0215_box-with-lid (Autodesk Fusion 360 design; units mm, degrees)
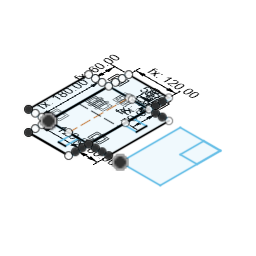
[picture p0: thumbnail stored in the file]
parameter "length" = 180
parameter "width" = 120
parameter "height" = 60
parameter "thickness" = 4.4
sketch "Sketch1" plane through (0, 0, 0) normal (0, 0, 1) x axis (1, 0, 0)
  line L1 (120, 0) -> (0, 0)
  line L2 (120, 180) -> (120, 0)
  line L3 (0, 180) -> (120, 180)
  line L4 (0, 0) -> (0, 180)
  line L5 (180, 0) -> (120, 0)
  line L6 (180, 180) -> (180, 0)
  line L7 (120, 180) -> (180, 180)
  line L8 (120, 0) -> (120, 180)
  line L9 (120, 240) -> (120, 180)
  line L10 (0, 240) -> (120, 240)
  line L11 (0, 180) -> (0, 240)
  line L12 (120, 184.4) -> (120, 180)
  line L13 (130, 184.4) -> (120, 184.4)
  line L14 (130, 180) -> (130, 184.4)
  line L15 (140, 180) -> (130, 180)
  line L16 (150, 184.4) -> (140, 184.4)
  line L17 (150, 180) -> (150, 184.4)
  line L18 (160, 180) -> (150, 180)
  line L19 (140, 184.4) -> (140, 180)
  line L20 (170, 184.4) -> (160, 184.4)
  line L21 (170, 180) -> (170, 184.4)
  line L22 (180, 180) -> (170, 180)
  line L23 (160, 184.4) -> (160, 180)
  line L24 (120, 190) -> (120, 180)
  line L25 (124.4, 190) -> (120, 190)
  line L26 (124.4, 200) -> (124.4, 190)
  line L27 (120, 200) -> (124.4, 200)
  line L28 (120, 210) -> (120, 200)
  line L29 (124.4, 210) -> (120, 210)
  line L30 (124.4, 220) -> (124.4, 210)
  line L31 (120, 220) -> (124.4, 220)
  line L32 (120, 230) -> (120, 220)
  line L33 (124.4, 230) -> (120, 230)
  line L34 (124.4, 240) -> (124.4, 230)
  line L35 (120, 240) -> (124.4, 240)
  line L36 (120, 90) -> (0, 90)
  line L37 (60, 0) -> (60, 180)
  line L38 (-60, 0) -> (0, 0)
  line L39 (-60, 180) -> (-60, 0)
  line L40 (0, 180) -> (-60, 180)
  line L41 (0, 0) -> (0, 180)
  line L42 (120, -60) -> (120, 0)
  line L43 (0, -60) -> (120, -60)
  line L44 (0, 0) -> (0, -60)
  line L45 (0, 210) -> (0, 200)
  line L46 (0, 190) -> (0, 180)
  line L47 (-4.4, 200) -> (-4.4, 190)
  line L48 (-4.4, 220) -> (-4.4, 210)
  line L49 (-10, 184.4) -> (0, 184.4)
  line L50 (-40, 180) -> (-30, 180)
  line L51 (0, 230) -> (0, 220)
  line L52 (-4.4, 230) -> (0, 230)
  line L53 (-50, 184.4) -> (-40, 184.4)
  line L54 (-20, 184.4) -> (-20, 180)
  line L55 (0, 220) -> (-4.4, 220)
  line L56 (-40, 184.4) -> (-40, 180)
  line L57 (-4.4, 210) -> (0, 210)
  line L58 (0, 240) -> (-4.4, 240)
  line L59 (-30, 184.4) -> (-20, 184.4)
  line L60 (-50, 180) -> (-50, 184.4)
  line L61 (-60, 180) -> (-50, 180)
  line L62 (-10, 180) -> (-10, 184.4)
  line L63 (-4.4, 190) -> (0, 190)
  line L64 (0, 184.4) -> (0, 180)
  line L65 (0, 200) -> (-4.4, 200)
  line L66 (-20, 180) -> (-10, 180)
  line L67 (-4.4, 240) -> (-4.4, 230)
  line L68 (-30, 180) -> (-30, 184.4)
  line L69 (130, -4.4) -> (120, -4.4)
  line L70 (-4.4, -20) -> (-4.4, -10)
  line L71 (-4.4, -40) -> (-4.4, -30)
  line L72 (140, -4.4) -> (140, 0)
  line L73 (170, 0) -> (170, -4.4)
  line L74 (124.4, -50) -> (120, -50)
  line L75 (124.4, -60) -> (124.4, -50)
  line L76 (124.4, -30) -> (120, -30)
  line L77 (180, 0) -> (170, 0)
  line L78 (150, -4.4) -> (140, -4.4)
  line L79 (0, -40) -> (-4.4, -40)
  line L80 (-10, 0) -> (-10, -4.4)
  line L81 (0, -30) -> (0, -20)
  line L82 (120, -20) -> (124.4, -20)
  line L83 (0, -10) -> (0, 0)
  line L84 (150, 0) -> (150, -4.4)
  line L85 (-4.4, -60) -> (-4.4, -50)
  line L86 (-4.4, -30) -> (0, -30)
  line L87 (-30, 0) -> (-30, -4.4)
  line L88 (124.4, -10) -> (120, -10)
  line L89 (140, 0) -> (130, 0)
  line L90 (160, 0) -> (150, 0)
  line L91 (0, -60) -> (-4.4, -60)
  line L92 (-20, 0) -> (-10, 0)
  line L93 (120, -4.4) -> (120, 0)
  line L94 (-4.4, -50) -> (0, -50)
  line L95 (-60, 0) -> (-50, 0)
  line L96 (-10, -4.4) -> (0, -4.4)
  line L97 (130, 0) -> (130, -4.4)
  line L98 (-40, -4.4) -> (-40, 0)
  line L99 (120, -50) -> (120, -40)
  line L100 (0, -4.4) -> (0, 0)
  line L101 (160, -4.4) -> (160, 0)
  line L102 (120, -10) -> (120, 0)
  line L103 (-40, 0) -> (-30, 0)
  line L104 (-20, -4.4) -> (-20, 0)
  line L105 (124.4, -40) -> (124.4, -30)
  line L106 (-50, 0) -> (-50, -4.4)
  line L107 (170, -4.4) -> (160, -4.4)
  line L108 (0, -60) -> (120, -60)
  line L109 (0, -20) -> (-4.4, -20)
  line L110 (120, -30) -> (120, -20)
  line L111 (0, -50) -> (0, -40)
  line L112 (124.4, -20) -> (124.4, -10)
  line L113 (-50, -4.4) -> (-40, -4.4)
  line L114 (-4.4, -10) -> (0, -10)
  line L115 (120, -40) -> (124.4, -40)
  line L116 (120, -60) -> (124.4, -60)
  line L117 (-30, -4.4) -> (-20, -4.4)
  line L118 (90, 0) -> (70, 0)
  line L119 (90, -40) -> (90, 0)
  line L120 (70, -40) -> (90, -40)
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  point P1 (0, 0)
  point P2 (0, 0)
  point P40 (0, 90)
  point P41 (120, 90)
  point P43 (60, 0)
  point P4 (120, 180)
  point P73 (0, 180)
  point P7 (180, 180)
  point P82 (-60, 180)
  point P8 (120, 180)
  point P56 (0, 180)
  point P9 (120, 180)
  point P78 (0, 180)
  point P10 (120, 240)
  point P60 (0, 240)
  point P12 (120, 184.4)
  point P64 (0, 184.4)
  point P13 (130, 184.4)
  point P66 (-10, 184.4)
  point P14 (130, 180)
  point P58 (-10, 180)
  point P15 (140, 180)
  point P77 (-20, 180)
  point P16 (140, 184.4)
  point P80 (-20, 184.4)
  point P17 (150, 184.4)
  point P68 (-30, 184.4)
  point P18 (150, 180)
  point P67 (-30, 180)
  point P19 (160, 180)
  point P51 (-40, 180)
  point P20 (140, 180)
  point P75 (-20, 180)
  point P21 (160, 184.4)
  point P65 (-40, 184.4)
  point P22 (170, 184.4)
  point P63 (-50, 184.4)
  point P23 (170, 180)
  point P62 (-50, 180)
  point P24 (180, 180)
  point P55 (-60, 180)
  point P25 (160, 180)
  point P81 (-40, 180)
  point P26 (120, 190)
  point P61 (0, 190)
  point P27 (124.4, 190)
  point P79 (-4.4, 190)
  point P28 (124.4, 200)
  point P74 (-4.4, 200)
  point P29 (120, 200)
  point P54 (0, 200)
  point P30 (120, 200)
  point P76 (0, 200)
  point P31 (120, 210)
  point P69 (0, 210)
  point P32 (124.4, 210)
  point P70 (-4.4, 210)
  point P33 (124.4, 220)
  point P71 (-4.4, 220)
  point P34 (120, 220)
  point P53 (0, 220)
  point P35 (120, 220)
  point P57 (0, 220)
  point P36 (120, 230)
  point P50 (0, 230)
  point P37 (124.4, 230)
  point P72 (-4.4, 230)
  point P38 (124.4, 240)
  point P52 (-4.4, 240)
  point P39 (120, 240)
  point P59 (0, 240)
  point P139 (120, 0)
  point P5 (0, 180)
  point P106 (0, 0)
  point P105 (180, 0)
  point P137 (120, 0)
  point P138 (120, 0)
  point P87 (120, -60)
  point P11 (0, 240)
  point P86 (0, -60)
  point P136 (120, -4.4)
  point P135 (130, -4.4)
  point P134 (130, 0)
  point P115 (140, 0)
  point P94 (140, -4.4)
  point P124 (150, -4.4)
  point P120 (150, 0)
  point P100 (160, 0)
  point P150 (140, 0)
  point P127 (160, -4.4)
  point P143 (170, -4.4)
  point P102 (170, 0)
  point P112 (180, 0)
  point P118 (160, 0)
  point P126 (120, -10)
  point P123 (124.4, -10)
  point P152 (124.4, -20)
  point P97 (120, -20)
  point P104 (120, -20)
  point P140 (120, -30)
  point P96 (124.4, -30)
  point P151 (124.4, -40)
  point P146 (120, -40)
  point P147 (120, -40)
  point P132 (120, -50)
  point P117 (124.4, -50)
  point P83 (124.4, -60)
  point P88 (120, -60)
  point P42 (60, 180)
  point P131 (60, 0)
  point P45 (-60, 180)
  point P107 (-60, 0)
  point P46 (0, 180)
  point P111 (0, 0)
  point P144 (0, -50)
  point P125 (-40, 0)
  point P85 (-4.4, -60)
  point P130 (0, -40)
  point P103 (0, -20)
  point P101 (-60, 0)
  point P121 (0, 0)
  point P91 (0, -40)
  point P98 (-10, 0)
  point P84 (0, -60)
  point P89 (0, -60)
  point P93 (0, -10)
  point P122 (-50, 0)
  point P128 (-50, -4.4)
  point P145 (0, -4.4)
  point P90 (-40, -4.4)
  point P95 (-10, -4.4)
  point P110 (-30, 0)
  point P108 (-30, -4.4)
  point P109 (0, -30)
  point P92 (-4.4, -30)
  point P116 (-4.4, -40)
  point P153 (-4.4, -50)
  point P129 (0, 0)
  point P141 (-4.4, -20)
  point P133 (-20, 0)
  point P114 (0, -20)
  point P99 (-20, 0)
  point P149 (0, 0)
  point P148 (-4.4, -10)
  point P113 (-20, -4.4)
  point P142 (-40, 0)
  point P119 (-60, 0)
  point P154 (70, 0)
  point P158 (120, 133.0136)
  point P166 (0, 0)
  point P167 (0, 0)
  point P173 (214.1582, 0)
  point P175 (214.1582, 0)
  point P3 (120, 0)
  point P6 (180, 0)
  point P44 (-60, 0)
  point P49 (0, -60)
  point P155 (90, 0)
  point P157 (70, -40)
  point P159 (160, 133.0136)
  point P161 (120, 103.0136)
  point P164 (120, 0)
  point P162 (0, 180)
  point P163 (120, 180)
  point P165 (70, 180)
  point P168 (120, 110)
  point P171 (334.1582, 0)
  point P169 (214.1582, 180)
  point P170 (334.1582, 180)
  point P172 (284.1582, 180)
  point P176 (334.1582, 110)
  horizontal L1
  vertical L2
  horizontal L3
  vertical L4
  coincident P1 P2
  horizontal L5
  vertical L6
  horizontal L7
  vertical L8
  vertical L9
  horizontal L10
  vertical L11
  perpendicular L12 L13
  perpendicular L7 L14
  perpendicular L14 L15
  perpendicular L24 L25
  perpendicular L25 L26
  perpendicular L9 L27
  midpoint L4 P40
  midpoint L2 P41
  midpoint L1 P43
  horizontal L38
  vertical L39
  horizontal L40
  vertical L41
  vertical L42
  horizontal L43
  vertical L44
  symmetric P4 L37 P73
  symmetric P7 L37 P82
  symmetric P8 L37 P56
  symmetric P9 L37 P78
  symmetric P10 L37 P60
  symmetric P12 L37 P64
  symmetric P13 L37 P66
  symmetric P14 L37 P58
  symmetric P15 L37 P77
  symmetric P16 L37 P80
  symmetric P17 L37 P68
  symmetric P18 L37 P67
  symmetric P19 L37 P51
  symmetric P20 L37 P75
  symmetric P21 L37 P65
  symmetric P22 L37 P63
  symmetric P23 L37 P62
  symmetric P24 L37 P55
  symmetric P25 L37 P81
  symmetric P26 L37 P61
  symmetric P27 L37 P79
  symmetric P28 L37 P74
  symmetric P29 L37 P54
  symmetric P30 L37 P76
  symmetric P31 L37 P69
  symmetric P32 L37 P70
  symmetric P33 L37 P71
  symmetric P34 L37 P53
  symmetric P35 L37 P57
  symmetric P36 L37 P50
  symmetric P37 L37 P72
  symmetric P38 L37 P52
  symmetric P39 L37 P59
  symmetric P4 L36 P139
  symmetric P5 L36 P106
  symmetric P7 L36 P105
  symmetric P8 L36 P137
  symmetric P9 L36 P138
  symmetric P10 L36 P87
  symmetric P11 L36 P86
  symmetric P12 L36 P136
  symmetric P13 L36 P135
  symmetric P14 L36 P134
  symmetric P15 L36 P115
  symmetric P16 L36 P94
  symmetric P17 L36 P124
  symmetric P18 L36 P120
  symmetric P19 L36 P100
  symmetric P20 L36 P150
  symmetric P21 L36 P127
  symmetric P22 L36 P143
  symmetric P23 L36 P102
  symmetric P24 L36 P112
  symmetric P25 L36 P118
  symmetric P26 L36 P126
  symmetric P27 L36 P123
  symmetric P28 L36 P152
  symmetric P29 L36 P97
  symmetric P30 L36 P104
  symmetric P31 L36 P140
  symmetric P32 L36 P96
  symmetric P33 L36 P151
  symmetric P34 L36 P146
  symmetric P35 L36 P147
  symmetric P36 L36 P132
  symmetric P37 L36 P117
  symmetric P38 L36 P83
  symmetric P39 L36 P88
  symmetric L36 P42 P131
  symmetric L36 P45 P107
  symmetric L36 P46 P111
  symmetric L36 P50 P144
  symmetric L36 P51 P125
  symmetric L36 P52 P85
  symmetric L36 P53 P130
  symmetric L36 P54 P103
  symmetric L36 P55 P101
  symmetric L36 P56 P121
  symmetric L36 P57 P91
  symmetric L36 P58 P98
  symmetric L36 P59 P84
  symmetric L36 P60 P89
  symmetric L36 P61 P93
  symmetric L36 P62 P122
  symmetric L36 P63 P128
  symmetric L36 P64 P145
  symmetric L36 P65 P90
  symmetric L36 P66 P95
  symmetric L36 P67 P110
  symmetric L36 P68 P108
  symmetric L36 P69 P109
  symmetric L36 P70 P92
  symmetric L36 P71 P116
  symmetric L36 P72 P153
  symmetric L36 P73 P129
  symmetric L36 P74 P141
  symmetric L36 P75 P133
  symmetric L36 P76 P114
  symmetric L36 P77 P99
  symmetric L36 P78 P149
  symmetric L36 P79 P148
  symmetric L36 P80 P113
  symmetric L36 P81 P142
  symmetric L36 P82 P119
  horizontal L118
  vertical L119
  horizontal L120
  coincident L1 P154
  coincident L2 P158
  coincident P166 P167
  coincident P173 P175
  dimension "d4" distance P2 P3 = 120 (= "width")
  dimension "d5" distance P2 P5 = 180 (= "length")
  dimension "d6" distance P3 P6 = 60 (= "height")
  dimension "d7" distance P3 P8 = 180 (= "length")
  dimension "d10" distance P5 P9 = 120 (= "width")
  dimension "d11" distance P5 P11 = 60 (= "height")
  dimension "d16" distance P8 P12 = 4.4 (= "thickness")
  dimension "d17" distance P12 P13 = 10 (= "height / ( 2 * num_fingers )")
  dimension "d18" distance P13 P14 = 4.4 (= "thickness")
  dimension "d19" distance P14 P15 = 10 (= "height / ( 2 * num_fingers )")
  dimension "d28" distance P8 P26 = 10 (= "height / ( 2 * num_fingers )")
  dimension "d29" distance P26 P27 = 4.4 (= "thickness")
  dimension "d31" distance P27 P28 = 10 (= "height / ( 2 * num_fingers )")
  dimension "d32" distance P28 P29 = 4.4 (= "thickness")
  dimension "d37" distance P2 P44 = 60 (= "height")
  dimension "d38" distance P2 P46 = 180 (= "length")
  dimension "d39" distance P2 P49 = 60 (= "height")
  dimension "d40" distance P154 P155 = 20
  dimension "d41" distance P154 P157 = 40
  dimension "d42" distance P158 P159 = 40
  dimension "d43" distance P158 P161 = 30
  dimension "d44" distance P164 P167 = 120
  dimension "d45" distance P162 P167 = 180
  dimension "d46" distance P163 P165 = 50
  dimension "d47" distance P163 P168 = 70
  dimension "d48" distance P171 P175 = 120
  dimension "d49" distance P169 P175 = 180
  dimension "d50" distance P170 P172 = 50
  dimension "d51" distance P170 P176 = 70
  dimension "d22" R-Pattern1-uDistance = 20 (= "height / num_fingers")
  dimension "d23" R-Pattern1-vDistance = 0
  dimension "d26" R-Pattern2-uDistance = 20 (= "height / num_fingers")
  dimension "d27" R-Pattern2-vDistance = 0
  dimension "d35" R-Pattern3-uDistance = 0
  dimension "d36" R-Pattern3-vDistance = 20 (= "height / num_fingers")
